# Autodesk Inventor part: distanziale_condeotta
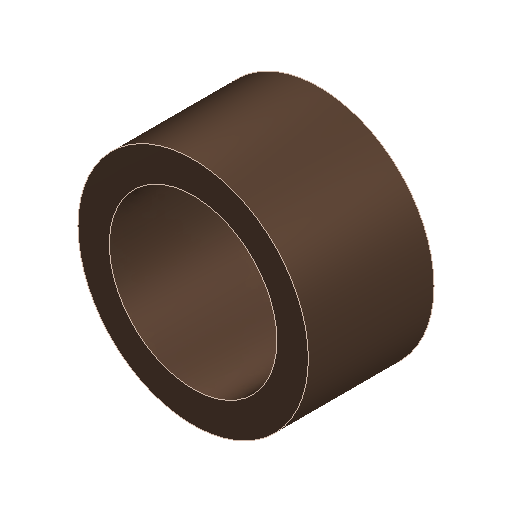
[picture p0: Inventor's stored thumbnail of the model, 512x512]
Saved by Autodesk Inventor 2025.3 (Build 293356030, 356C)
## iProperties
Created: 2026-05
Part Number: distanziale_condeotta
Material: Bronzo, Stagno dolce
Document SubType Name: Modeling
Designer: R5800u
Density: 8.874 g/cm^3
Appearance: Bronzo - Satinato
Author: R5800u
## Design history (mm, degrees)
sketch "Schizzo1"
  geometry: C1 r 20 at (0, 0); C2 r 27.5 at (0, 0); 1 further point
  constraints: 2 centre point, 1 coincident
  dimensions: "d0" = 40 diameter of C1; "d1" = 7.5 radial gap between concentric circles of C1 C2
extrude "Estrusione1" new body sketch "Schizzo1" distance "d2" = 30; taper "d3" = 0 deg
node "Solido1"
